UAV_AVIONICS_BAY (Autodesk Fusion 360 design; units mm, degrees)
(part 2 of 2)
extrude "Extrude1" new body sketch "SK_Fastener_Head" along normal blind 0.6
sketch "SK_Fastener_Shank" plane through (0, 0, 0) normal (0, 0, 1) x axis (1, 0, 0)
  circle C1 centre (0, 0) radius 1.25
extrude "Extrude2" add sketch "SK_Fastener_Shank" against normal blind 2
copy_paste "CopyPaste111"
copy_paste "CopyPaste112"
copy_paste "CopyPaste113"
ground "Pin1"
ground "Pin2"
as_built_joint "As-built1"
as_built_joint "As-built2"
as_built_joint "As-built3"
as_built_joint "As-built4"
joint_origin "JointOrigin1" OffsetX 0 OffsetY 0 OffsetZ 0 AngleZ 0
as_built_joint "As-built1" SlideMinimum 0 SlideMaximum 40
joint_origin "JointOrigin1" OffsetX 0 OffsetY 0 OffsetZ 0 AngleZ 0
as_built_joint "As-built1" RotateMinimum 0 RotateMaximum 95
joint_origin "JointOrigin1" OffsetX 0 OffsetY 0 OffsetZ 0 AngleZ 0
as_built_joint "As-built2" SlideMinimum 0 SlideMaximum 30
joint_origin "JointOrigin1" OffsetX 0 OffsetY 0 OffsetZ 0 AngleZ 0
as_built_joint "As-built3" SlideMinimum 0 SlideMaximum 45
joint_origin "JointOrigin1" OffsetX 0 OffsetY 0 OffsetZ 0 AngleZ 0
as_built_joint "As-built4" SlideMinimum -15 SlideMaximum 0
as_built_joint "As-built5"
as_built_joint "As-built6"
as_built_joint "As-built7"
as_built_joint "As-built8"
as_built_joint "As-built9"
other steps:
create_component "CreateComponent1"
create_component "CreateComponent2"
create_component "CreateComponent3"
create_component "CreateComponent4"
create_component "CreateComponent5"
create_component "CreateComponent6"
create_component "CreateComponent7"
create_component "CreateComponent8"
create_component "CreateComponent1"
create_component "CreateComponent2"
create_component "CreateComponent3"
create_component "CreateComponent4"
create_component "CreateComponent5"
create_component "CreateComponent1"
create_component "CreateComponent2"
create_component "CreateComponent3"
create_component "CreateComponent1"
create_component "CreateComponent2"
create_component "CreateComponent3" sketch "SK_PDB-03-303_Deck_Standoff_M2_5x6_Body"
create_component "CreateComponent4" sketch "SK_PDB-03-304_PCB_Standoff_M2x4_Body"
create_component "CreateComponent1"
create_component "CreateComponent2"
create_component "CreateComponent3"
create_component "CreateComponent4"
create_component "CreateComponent5"
create_component "CreateComponent6"
create_component "CreateComponent1"
create_component "CreateComponent2"
create_component "CreateComponent3"
create_component "CreateComponent4"
create_component "CreateComponent1"
create_component "CreateComponent2"
create_component "CreateComponent3"
create_component "CreateComponent4"
create_component "CreateComponent1"
create_component "CreateComponent2"
create_component "CreateComponent3"
create_component "CreateComponent4"
create_component "CreateComponent1"
create_component "CreateComponent2" sketch "SK_Hardware_Ring"
create_component "CreateComponent3" sketch "SK_Hardware_Ring"
create_component "CreateComponent4"
create_component "CreateComponent5" sketch "SK_Hardware_Ring"
create_component "CreateComponent6"
create_component "CreateComponent7"
create_component "CreateComponent8"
